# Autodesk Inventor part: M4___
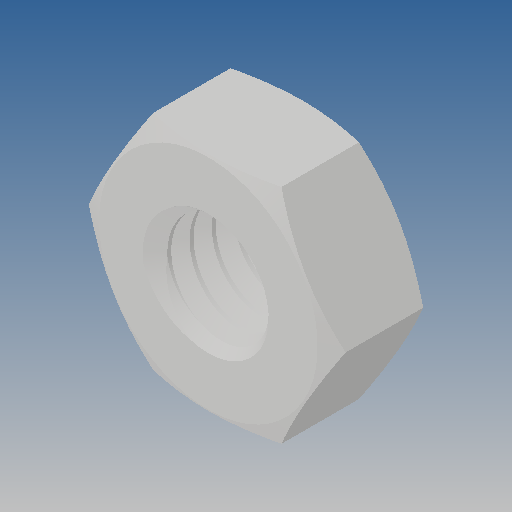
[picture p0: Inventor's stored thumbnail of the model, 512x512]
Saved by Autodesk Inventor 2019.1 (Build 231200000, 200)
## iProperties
Created: 2010-06
Part Number: M4___
Material: Ogólny
Document SubType Name: Modeling
Designer: CADENGINEERING4
Density: 1 g/cm^3
Appearance: Domyślna
Author: CADENGINEERING4
Revision Number: ANY
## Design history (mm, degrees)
feature "NONE"
node "Bryła1"
